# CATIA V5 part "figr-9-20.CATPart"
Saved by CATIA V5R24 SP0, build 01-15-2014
Part number: Part3
Bounding box of the stored display mesh (mm): x -112 to 0, y -101.683 to 100, z -80.304 to 44.415
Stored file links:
  D:\KAVITA\CATIA V5-6R2014 Project_ Kavita\CATIA V5-6R2014_partfiles\Partfiles\c09_catia_v5-6r2014_prt\figr-9-20.CATPart
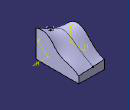
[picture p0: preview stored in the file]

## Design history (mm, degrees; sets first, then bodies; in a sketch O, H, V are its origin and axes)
Set1
  Plane1: type Offset, RefPlane yz-plane, Offset -112
  Plane2: type Offset, RefPlane yz-plane, Offset -63
  Plane3: type Normal, Curve Sketch4, RefPoint vertex of Sketch4
Body1 (main body)
  Sketch1 on yz-plane, origin (0, 0, 0), H (0, 1, 0), V (0, 0, 1)
    spline S1 through (-92.6897, 40.1119) (-30, 30) (10, -10) (60, -30) (97.3103, -50.3041)
    line L1 (97.3103, -50.3041) -> (97.3103, -80.3041)
    line L2 (97.3103, -80.3041) -> (-92.6897, -80.3041)
    line L3 (-92.6897, -80.3041) -> (-92.6897, 40.1119)
    point P3 (-92.6897, 40.1119)
    point P4 (97.3103, -50.3041)
    point P5 (-92.6897, 40.1119)
    point P6 (97.3103, -50.3041)
    vertical: L1 V, L3 V
    horizontal: L2 H
    coincidence: P5 P3, P6 P4
  Sketch2 on Plane1, origin (-112, 0, 0), H (0, 1, 0), V (0, 0, 1)
    spline S1 through (-90, -30) (-70, 10) (-20, 40) (40, 0) (100, -40)
    line L1 (100, -40) -> (100, -80)
    line L2 (100, -80) -> (-90, -80)
    line L3 (-90, -80) -> (-90, -30)
    point P3 (-90, -30)
    point P4 (100, -40)
    point P5 (40, 0)
    point P6 (-90, -30)
    point P7 (100, -40)
    coincidence: P5 H, P6 P3, P7 P4
    vertical: L1 V, L3 V
    horizontal: L2 H
  Loft1: Sections (Sketch1; Sketch2)
  Sketch3 on Plane3, origin (0, -40.1726, -44.9298), H (1, 0, 0), V (0, -0.7455, 0.6665)
    point P1 (-63, 68.4187)
    line L1 (-63, 68.4187) -> (-75.2117, 62.4925)
    line L2 (-75.2117, 62.4925) -> (-79.6266, 71.5898)
    line L3 (-79.6266, 71.5898) -> (-57.1205, 82.5119)
    line L4 (-57.1205, 82.5119) -> (-52.7056, 73.4145)
    point P5 (-52.7056, 73.4145)
    line L5 (-52.7056, 73.4145) -> (-63, 68.4187)
    reference projected point E1 (-63, 68.4187) from vertex of Sketch4
    perpendicularity: L2 L1
    parallelism: L3 L1, L4 L2, L5 L1
    coincidence: P5 L1, P1 E1
  Sketch4 on Plane2, origin (-63, 0, 0), H (0, 1, 0), V (0, 0, 1)
    intersected curve E1 from face of Loft1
